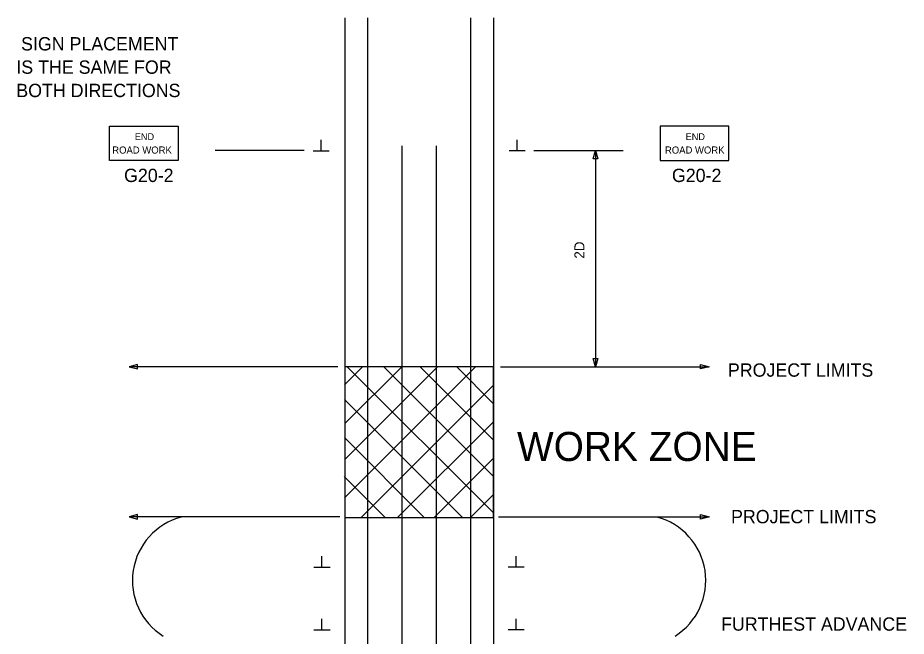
# Model space of a CAD drawing. Extents: x 19023 to 20762, y 4888 to 6104.
# Drawn here: x 19070 to 19691, y 5672 to 6104 of the extents above; entities that cross this region are included whole.
import ezdxf

# ---------------------------------------------------------------- set-up
doc = ezdxf.new("R2010")
doc.units = 0
for name, color, linetype in [('BORDER', 7, 'Continuous'), ('PAVT_EDGE_EX', 7, 'Continuous'), ('TRAFFIC_SIGNS_PR', 7, 'Continuous'), ('TYPICAL_TEXT_DIMEN_PR', 7, 'Continuous')]:
    doc.layers.add(name, color=color, linetype=linetype)

msp = doc.modelspace()

# ---------------------------------------------------------------- linework, layer by layer
at = {"layer": 'BORDER'}
msp.add_line((19298.936, 5685.504), (19298.936, 5685.504), dxfattribs=at)
at = {"layer": 'PAVT_EDGE_EX'}
for p, q in [((19298.917, 6104.026), (19298.917, 5261.047)), ((19314.917, 6104.026), (19314.917, 5261.047)), ((19386.917, 6104.026), (19386.917, 5261.047)), ((19402.917, 6104.026), (19402.917, 5261.047)), ((19338.917, 6014.455), (19338.917, 5261.047)), ((19362.917, 6014.455), (19362.917, 5261.047)), ((19298.779, 5768.582), (19390.402, 5860.205)), ((19298.888, 5847.506), (19311.63, 5860.248)), ((19402.917, 5860.205), (19299.068, 5860.205)), ((19402.917, 5783.445), (19325.959, 5860.403)), ((19402.917, 5808.901), (19351.371, 5860.447)), ((19386.917, 5860.676), (19386.917, 5754.897)), ((19402.917, 5859.812), (19402.524, 5860.205)), ((19402.917, 5754.897), (19402.917, 5860.205)), ((19299.107, 5820.508), (19338.599, 5860)), ((19299.137, 5795.458), (19363.651, 5859.972)), ((19402.853, 5758.053), (19300.735, 5860.171)), ((19402.917, 5834.356), (19377.21, 5860.063)), ((19310.288, 5754.636), (19402.917, 5847.265)), ((19381.047, 5755.023), (19298.828, 5837.242)), ((19336.16, 5755.052), (19402.917, 5821.809)), ((19354.568, 5754.958), (19298.806, 5810.72)), ((19361.483, 5754.919), (19402.917, 5796.353)), ((19327.047, 5755.123), (19298.624, 5783.546)), ((19386.917, 5754.897), (19402.917, 5770.897)), ((19298.857, 5754.897), (19402.888, 5754.897)), ((19386.917, 5754.897), (19402.917, 5754.897)), ((19386.917, 5754.897), (19386.917, 5754.897))]:
    msp.add_line(p, q, dxfattribs=at)
for points in [[(19338.917, 6014.455), (19338.917, 5989.455)], [(19338.917, 6014.455), (19338.917, 5989.455)], [(19362.917, 6014.455), (19362.917, 5989.455)], [(19338.917, 5914.455), (19338.917, 5889.455)], [(19362.917, 5914.455), (19362.917, 5889.455)], [(19338.917, 5714.455), (19338.917, 5689.455)], [(19362.917, 5714.455), (19362.917, 5689.455)]]:
    msp.add_lwpolyline(points, dxfattribs=at)
at = {"layer": 'TYPICAL_TEXT_DIMEN_PR'}
for p, q in [((19282.44, 6011.039), (19282.44, 6018.824)), ((19419.394, 6011.039), (19419.394, 6018.824)), ((19270.702, 6011.246), (19208.388, 6011.246)), ((19276.815, 6011.039), (19282.44, 6011.039)), ((19282.44, 6011.039), (19288.065, 6011.039)), ((19419.394, 6011.039), (19413.769, 6011.039)), ((19425.019, 6011.039), (19419.394, 6011.039)), ((19431.132, 6011.246), (19493.446, 6011.246)), ((19472.574, 6005.484), (19474.145, 6011.346)), ((19474.135, 6011.141), (19474.135, 5860.357)), ((19474.145, 6011.346), (19475.716, 6005.484)), ((19474.145, 6005.484), (19472.574, 6005.484)), ((19475.716, 6005.484), (19474.145, 6005.484)), ((19154.219, 5861.764), (19148.357, 5860.193)), ((19294.039, 5860.193), (19148.357, 5860.193)), ((19148.357, 5860.193), (19154.219, 5858.622)), ((19154.219, 5860.193), (19154.219, 5861.764)), ((19154.219, 5858.622), (19154.219, 5860.193)), ((19407.795, 5860.193), (19553.477, 5860.193)), ((19474.146, 5860.18), (19472.575, 5866.042)), ((19472.575, 5866.042), (19474.146, 5866.042)), ((19474.146, 5866.042), (19475.717, 5866.042)), ((19475.717, 5866.042), (19474.146, 5860.18)), ((19547.615, 5860.193), (19547.615, 5861.764)), ((19547.615, 5861.764), (19553.477, 5860.193)), ((19553.477, 5860.193), (19547.615, 5858.622)), ((19547.615, 5858.622), (19547.615, 5860.193)), ((19154.219, 5756.863), (19148.357, 5755.292)), ((19295.524, 5755.292), (19148.357, 5755.292)), ((19148.357, 5755.292), (19154.219, 5753.721)), ((19154.219, 5755.292), (19154.219, 5756.863)), ((19154.219, 5753.721), (19154.219, 5755.292)), ((19406.31, 5755.292), (19553.477, 5755.292)), ((19547.615, 5755.292), (19547.615, 5756.863)), ((19547.615, 5756.863), (19553.477, 5755.292)), ((19553.477, 5755.292), (19547.615, 5753.721)), ((19547.615, 5753.721), (19547.615, 5755.292)), ((19283.058, 5720.103), (19283.058, 5727.888)), ((19418.776, 5720.103), (19418.776, 5727.888)), ((19277.433, 5720.103), (19283.058, 5720.103)), ((19283.058, 5720.103), (19288.683, 5720.103)), ((19418.776, 5720.103), (19413.151, 5720.103)), ((19424.401, 5720.103), (19418.776, 5720.103)), ((19283.057, 5676.281), (19283.057, 5684.066)), ((19418.777, 5676.281), (19418.777, 5684.066)), ((19277.432, 5676.281), (19283.057, 5676.281)), ((19283.057, 5676.281), (19288.682, 5676.281)), ((19418.777, 5676.281), (19413.152, 5676.281)), ((19424.402, 5676.281), (19418.777, 5676.281))]:
    msp.add_line(p, q, dxfattribs=at)
for points in [[(19182.549, 6004.276), (19134.549, 6004.276), (19134.549, 6028.276), (19182.549, 6028.276)], [(19519.285, 6004.276), (19567.285, 6004.276), (19567.285, 6028.276), (19519.285, 6028.276)]]:
    msp.add_lwpolyline(points, close=True, dxfattribs=at)
for centre, start, end in [((19196.434, 5710.817), 104.748278, 237.843711), ((19505.4, 5710.817), 302.156289, 75.251722)]:
    msp.add_arc(centre, 45.823, start, end, dxfattribs=at)

# ---------------------------------------------------------------- texts
at = {"layer": 'TRAFFIC_SIGNS_PR'}
for s, p in [('SIGN PLACEMENT', (19072.815, 6081.187)), ('IS THE SAME FOR', (19069.497, 6064.887)), ('BOTH DIRECTIONS', (19069.476, 6048.587)), ('G20-2', (19144.77, 5989.252)), ('G20-2', (19527.569, 5989.252)), ('PROJECT LIMITS', (19566.684, 5853.237)), ('PROJECT LIMITS', (19568.872, 5750.817)), ('FURTHEST ADVANCE', (19561.911, 5675.776))]:
    msp.add_text(s, height=9.3, dxfattribs=at).set_placement(p)
at = {"layer": 'TYPICAL_TEXT_DIMEN_PR'}
for s, height, p in [('END', 4.79, (19152.256, 6018.529)), ('END', 4.79, (19537.132, 6018.529)), ('ROAD WORK', 4.956, (19136.525, 6009.129)), ('ROAD WORK', 4.956, (19522.695, 6009.129)), ('WORK ZONE', 20.309, (19419.304, 5794.349))]:
    msp.add_text(s, height=height, dxfattribs=at).set_placement(p)
msp.add_text('2D', height=7, rotation=90, dxfattribs=at).set_placement((19466.409, 5935.723))

doc.saveas('drawing.dxf')
